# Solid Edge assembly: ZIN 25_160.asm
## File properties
Title: Zylinder
Author: bmolnar
Template: iso metric assembly.asm
Last saved by: bmolnar
Revision: 30
Application: Solid Edge
Username: bmolnar
Dokumentum tartalom típus: 1
Document Number: ZIN 25/160
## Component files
Kit_1.par
Kit_2.par
Profilrohr.par
Kolbenstange.par
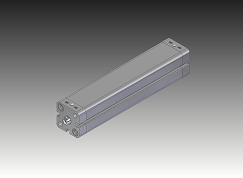
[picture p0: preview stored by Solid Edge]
